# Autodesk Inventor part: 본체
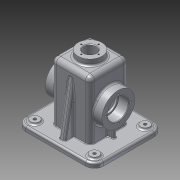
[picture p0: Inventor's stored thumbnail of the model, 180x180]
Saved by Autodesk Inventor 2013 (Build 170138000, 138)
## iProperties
Created: 2016-01
Part Number: 본체
Material: 알루미늄 6061
Document SubType Name: Modeling
Designer: Administrator
Density: 2.71 g/cm^3
Mass: 862.386 g
Surface Area: 914.264 cm^2
Volume: 318.224 cm^3
Author: Administrator
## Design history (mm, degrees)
sketch "스케치2"
  geometry: L1 (-32.5, 32.5)-(32.5, 32.5); L2 (32.5, 32.5)-(32.5, -32.5); L3 (32.5, -32.5)-(-32.5, -32.5); L4 (-32.5, -32.5)-(-32.5, 32.5); 3 further points
  constraints: 8 end point, 2 midpoint, 2 parallel, 1 horizontal, 1 horizontal alignment, 1 perpendicular, 1 vertical alignment
  dimensions: "d3" = 65 distance of L1.start L1.end; "d5" = 65 distance of L1.end L2.end
extrude "돌출1" new body sketch "스케치2" distance "d6" = 98; taper "d7" = 0 deg
sketch "스케치4"
  geometry: L1 (32.5, 98)-(32.5, 0) reference; L2 (32.5, 0)-(-32.5, 0) reference; L3 (-32.5, 0)-(-32.5, 98) reference; L4 (-32.5, 98)-(32.5, 98) reference; L5 (27.5, 93)-(27.5, 0); L6 (-27.5, 0)-(-27.5, 93); L7 (-27.5, 93)-(27.5, 93); 1 further point
  constraints: 6 end point, 2 point on line, 1 vertical, 1 other
  dimensions: "d10" = 5 distance between parallel lines of L3 L6; "d11" = 5 distance between parallel lines of L1 L5
extrude "돌출2" cut sketch "스케치4" stored distance "d12" = 55; taper "d13" = 0 deg
sketch "스케치5"
  geometry: C1 r 20 at (0, 0); 1 further point
  constraints: 1 centre point, 1 coincident
  dimensions: "d14" = 40 diameter of C1
extrude "돌출3" join sketch "스케치5" distance "d15" = 10; taper "d16" = 0 deg
hole "구멍1" diameter "d19" = 21; stored, may be unused: countersink angle "d23" = 90 deg, drill point angle "d25" = 0 deg; dims "d17" = 10, "d18" = 10, "d20" = 6, "d21" = 4, "d22" = 2, "d24" = 8
sketch "스케치7"
  geometry: L1 (-27.5, -27.5)-(27.5, -27.5) reference; L2 (27.5, -27.5)-(27.5, 27.5) reference; L3 (27.5, 27.5)-(-27.5, 27.5) reference; L4 (-27.5, 27.5)-(-27.5, -27.5) reference; L5 (32.5, 32.5)-(32.5, -32.5) reference; L6 (32.5, -32.5)-(-32.5, -32.5) reference; L7 (-32.5, -32.5)-(-32.5, 32.5) reference; L8 (-32.5, 32.5)-(32.5, 32.5) reference; L9 (-65, -57.5)-(65, -57.5); L10 (65, -57.5)-(65, 57.5); L11 (65, 57.5)-(-65, 57.5); L12 (-65, 57.5)-(-65, -57.5); 3 further points
  constraints: 8 end point, 2 midpoint, 2 parallel, 1 horizontal, 1 horizontal alignment, 1 perpendicular, 1 vertical alignment
  dimensions: "d30" = 130 distance of L9.start L9.end; "d32" = 115 distance of L9.end L10.end
extrude "돌출5" join sketch "스케치7" distance "d33" = 8; taper "d34" = 0 deg
sketch "스케치9"
  geometry: L1 (-27.5, -27.5)-(-27.5, 27.5) reference; L2 (-27.5, 27.5)-(27.5, 27.5) reference; L3 (27.5, 27.5)-(27.5, -27.5) reference; L4 (27.5, -27.5)-(-27.5, -27.5) reference; L5 (-60, -52.5)-(60, -52.5); L6 (60, -52.5)-(60, 52.5); L7 (60, 52.5)-(-60, 52.5); L8 (-60, 52.5)-(-60, -52.5); 3 further points
  constraints: 8 end point, 2 midpoint, 2 parallel, 1 horizontal, 1 horizontal alignment, 1 perpendicular, 1 vertical alignment
  dimensions: "d35" = 120 distance of L6.end L7.end; "d37" = 105 distance of L7.end L5.start
extrude "돌출6" join sketch "스케치9" distance "d38" = 2; taper "d39" = 0 deg
fillet "모깎기3" dims "d45" = 15
sketch "스케치13"
  geometry: C1 r 7.5 at (-50, 42.5); C2 r 7.5 at (50, 42.5); C3 r 7.5 at (-50, -42.5); C4 r 7.5 at (50, -42.5); A1 r 15 centre (-50, 42.5) between (-50, 57.5) and (-65, 42.5) reference; A2 r 15 centre (-50, -42.5) between (-65, -42.5) and (-50, -57.5) reference; A3 r 15 centre (50, -42.5) between (50, -57.5) and (65, -42.5) reference; A4 r 15 centre (50, 42.5) between (65, 42.5) and (50, 57.5) reference; 1 further point
  constraints: 4 centre point, 4 coincident
  dimensions: "d46" = 15 diameter of C1; "d47" = 15 diameter of C2; "d48" = 15 diameter of C3; "d49" = 15 diameter of C4
extrude "돌출7" join sketch "스케치13" distance "d50" = 3; taper "d51" = 0 deg
fillet "모깎기4" dims "d52" = 10
hole "구멍2" diameter "d55" = 5; stored, may be unused: countersink angle "d59" = 90 deg, drill point angle "d61" = 0 deg; dims "d53" = 10, "d54" = 10, "d56" = 6, "d57" = 4, "d58" = 2, "d60" = 8
hole "구멍3" diameter "d64" = 5; stored, may be unused: countersink angle "d68" = 90 deg, drill point angle "d70" = 0 deg; dims "d62" = 10, "d63" = 10, "d65" = 6, "d66" = 4, "d67" = 2, "d69" = 8
fillet "모깎기5" dims "d71" = 8
fillet "모깎기6" dims "d72" = 8
node "작업 평면1"
sketch "스케치14"
  geometry: L1 (10, 67)-(10, -18) reference; C1 r 27.5 at (-45, 24.5); 2 further points
  constraints: 1 centre point, 1 horizontal alignment, 1 midpoint
  dimensions: "d74" = 55 diameter of C1; "d75" = 55 distance from line of L1 C1.centre
extrude "돌출8" join sketch "스케치14" stored distance "d76" = 3; taper "d77" = 0 deg
hole "구멍4" diameter "d80" = 30; stored, may be unused: countersink angle "d84" = 90 deg, drill point angle "d86" = 0 deg; dims "d78" = 10, "d79" = 10, "d81" = 6, "d82" = 35, "d83" = 17, "d85" = 8
sketch "스케치15"
  geometry: C1 r 17.5 at (0, 0) reference; 2 further points
  constraints: 1 horizontal alignment
  dimensions: "d87" = 21 distance of C1.centre point (-21, 0)
hole "구멍5" sketch "스케치15" at (-21, 0) diameter "d88" = 3.242; stored, may be unused: countersink angle "d92" = 90 deg, drill point angle "d94" = 118 deg; dims "d89" = 8, "d90" = 35, "d91" = 17, "d93" = 10
sketch "스케치17"
  geometry: C1 r 10.5 at (0, 0) reference; 1 further point
  constraints: 1 horizontal alignment
  dimensions: "d98" = 14.5 distance of C1.centre point (-14.5, 0)
hole "구멍6" sketch "스케치17" at (-14.5, 0) diameter "d99" = 2.459; stored, may be unused: countersink angle "d103" = 90 deg, drill point angle "d105" = 118 deg; dims "d100" = 7, "d101" = 35, "d102" = 17, "d104" = 9
sketch "스케치19"
  geometry: L1 (47.5, 17.5)-(32.5, 17.5) reference; L2 (32.5, 17.5)-(32.5, 0) reference; L3 (32.5, 0)-(65, 0) reference; L4 (65, 0)-(65, -8) reference; L5 (65, -8)-(60, -8) reference; L6 (60, -8)-(60, -10) reference; L7 (60, -10)-(27.5, -10) reference; L8 (27.5, -10)-(27.5, 30) reference; L9 (27.5, 30)-(30.5, 30) reference; L10 (30.5, 30)-(30.5, 27.5) reference; L11 (30.5, 27.5)-(47.5, 27.5) reference; L12 (47.5, 27.5)-(47.5, 25.621) reference; L13 (47.5, 25.621)-(37.5, 25.621) reference; L14 (37.5, 25.621)-(36.526, 24) reference; L15 (36.526, 24)-(37.5, 22.379) reference; L16 (37.5, 22.379)-(47.5, 22.379) reference; L17 (47.5, 22.379)-(47.5, 17.5) reference; L18 (-60, -10)-(-60, -8) reference; L19 (-60, -8)-(-65, -8) reference; L20 (-65, -8)-(-65, 0) reference; L21 (-65, 0)-(-32.5, 0) reference; L22 (-32.5, 0)-(-32.5, 17.5) reference; L23 (-32.5, 17.5)-(-47.5, 17.5) reference; L24 (-47.5, 17.5)-(-47.5, 22.379) reference; L25 (-47.5, 22.379)-(-37.5, 22.379) reference; L26 (-37.5, 22.379)-(-36.526, 24) reference; L27 (-36.526, 24)-(-37.5, 25.621) reference; L28 (-37.5, 25.621)-(-47.5, 25.621) reference; L29 (-47.5, 25.621)-(-47.5, 27.5) reference; L30 (-47.5, 27.5)-(-30.5, 27.5) reference; L31 (-30.5, 27.5)-(-30.5, 30) reference; L32 (-30.5, 30)-(-27.5, 30) reference; L33 (-27.5, 30)-(-27.5, -10) reference; L34 (-27.5, -10)-(-60, -10) reference; L35 (-10.5, 108)-(-10.5, 93) reference; L36 (-10.5, 93)-(-27.5, 93) reference; L37 (-27.5, 93)-(-27.5, 60) reference; L38 (-27.5, 60)-(-30.5, 60) reference; L39 (-30.5, 60)-(-30.5, 62.5) reference; L40 (-30.5, 62.5)-(-47.5, 62.5) reference; L41 (-47.5, 62.5)-(-47.5, 64.379) reference; L42 (-47.5, 64.379)-(-37.5, 64.379) reference; L43 (-37.5, 64.379)-(-36.526, 66) reference; L44 (-36.526, 66)-(-37.5, 67.621) reference; L45 (-37.5, 67.621)-(-47.5, 67.621) reference; L46 (-47.5, 67.621)-(-47.5, 72.5) reference; L47 (-47.5, 72.5)-(-32.5, 72.5) reference; L48 (-32.5, 72.5)-(-32.5, 90) reference; L49 (-24.5, 98)-(-20, 98) reference; L50 (-20, 98)-(-20, 108) reference; L51 (-20, 108)-(-15.73, 108) reference; L52 (-15.73, 108)-(-15.73, 99) reference; L53 (-15.73, 99)-(-14.5, 98.261) reference; L54 (-14.5, 98.261)-(-13.271, 99) reference; L55 (-13.271, 99)-(-13.271, 108) reference; L56 (-13.271, 108)-(-10.5, 108) reference; L57 (10.5, 93)-(10.5, 108) reference; L58 (10.5, 108)-(13.271, 108) reference; L59 (13.271, 108)-(13.271, 99) reference; L60 (13.271, 99)-(14.5, 98.261) reference; L61 (14.5, 98.261)-(15.73, 99) reference; L62 (15.73, 99)-(15.73, 108) reference; L63 (15.73, 108)-(20, 108) reference; L64 (20, 108)-(20, 98) reference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; A1 r 8 centre (-24.5, 90) between (-24.5, 98) and (-32.5, 90) reference; A2 r 8 centre (24.5, 90) between (32.5, 90) and (24.5, 98) reference; 1 further point
  constraints: 2 end point, 2 point on line, 1 vertical
  dimensions: "d111" = 15 distance between parallel lines of L79 L8
feature "리브1" sketch "스케치19" dims "d112" = 1, "d113" = 6, "d114" = 0, "d115" = 0, "d116" = 1, "d117" = 1
sketch "스케치20"
  geometry: L1 (52.5, -10)-(27.5, -10) reference; L2 (27.5, -10)-(27.5, 93) reference; L3 (27.5, 93)-(10.5, 93) reference; L4 (10.5, 93)-(10.5, 108) reference; L5 (10.5, 108)-(13.271, 108) reference; L6 (13.271, 108)-(13.271, 99) reference; L7 (13.271, 99)-(14.5, 98.261) reference; L8 (14.5, 98.261)-(15.73, 99) reference; L9 (15.73, 99)-(15.73, 108) reference; L10 (15.73, 108)-(20, 108) reference; L11 (20, 108)-(20, 98) reference; L12 (20, 98)-(24.5, 98) reference; L13 (32.5, 90)-(32.5, 0) reference; L14 (32.5, 0)-(57.5, 0) reference; L15 (57.5, 0)-(57.5, -8) reference; L16 (57.5, -8)-(52.5, -8) reference; L17 (52.5, -8)-(52.5, -10) reference; L18 (-27.5, -10)-(-52.5, -10) reference; L19 (-52.5, -10)-(-52.5, -8) reference; L20 (-52.5, -8)-(-57.5, -8) reference; L21 (-57.5, -8)-(-57.5, 0) reference; L22 (-57.5, 0)-(-32.5, 0) reference; L23 (-32.5, 0)-(-32.5, 90) reference; L24 (-24.5, 98)-(-20, 98) reference; L25 (-20, 98)-(-20, 108) reference; L26 (-20, 108)-(-15.73, 108) reference; L27 (-15.73, 108)-(-15.73, 99) reference; L28 (-15.73, 99)-(-14.5, 98.261) reference; L29 (-14.5, 98.261)-(-13.271, 99) reference; L30 (-13.271, 99)-(-13.271, 108) reference; L31 (-13.271, 108)-(-10.5, 108) reference; L32 (-10.5, 108)-(-10.5, 93) reference; L33 (-10.5, 93)-(-27.5, 93) reference; L34 (-27.5, 93)-(-27.5, -10) reference; L35 (32.5, 85.069)-(47.5, 0); A1 r 8 centre (24.5, 90) between (32.5, 90) and (24.5, 98) reference; A2 r 8 centre (-24.5, 90) between (-24.5, 98) and (-32.5, 90) reference; 1 further point
  constraints: 2 end point, 2 point on line
  dimensions: "d118" = 10 deg angle of L15 L35; "d119" = 10 distance from line of L15 L35.end
feature "리브2" sketch "스케치20" dims "d120" = 1, "d121" = 10, "d122" = 0, "d123" = 0, "d124" = 1, "d125" = 1
fillet "모깎기7" dims "d126" = 0.3
fillet "모깎기8" dims "d127" = 3
fillet "모깎기9" dims "d128" = 3
fillet "모깎기10" dims "d129" = 3
fillet "모깎기11" dims "d130" = 3
fillet "모깎기12" dims "d131" = 3
fillet "모깎기13" dims "d132" = 1
fillet "모깎기14" dims "d133" = 3
fillet "모깎기15" dims "d134" = 3
sketch "스케치22"
  geometry: L1 (18, 4.5)-(18, 44.5) reference; L2 (0, 57)-(-89, 57) reference; 2 further points
  constraints: 1 other
  dimensions: "d135" = 27 distance from line of L1 point (-9, 24.5); "d136" = 32.5 distance from line of L2 point (-9, 24.5)
feature "엠보싱1" sketch "스케치22" dims "d137" = 0.5, "d138" = 0
chamfer "모따기1" distance "d139" = 1; stored, may be unused: second distance "d140" = 2, angle "d141" = 45 deg
node "솔리드1"
mirror "대칭1"
pattern_circular "원형 패턴1" dims angle "d96" = 360 deg
mirror "대칭3"
pattern_circular "원형 패턴2" dims angle "d107" = 360 deg
mirror "대칭4"
mirror "대칭5"
node "절단 모서리 투영2"
node "절단 모서리 투영3"
node "절단 모서리 투영4"
node "절단 모서리 투영5"
other parameters: "d73" = 15, "d109" = 15
